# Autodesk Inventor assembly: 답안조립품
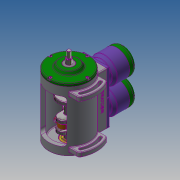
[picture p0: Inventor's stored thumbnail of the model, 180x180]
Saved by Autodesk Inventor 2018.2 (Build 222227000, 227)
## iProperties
Created: 2022-01
Part Number: 답안조립품
Document SubType Name: Assembly
Designer: woori
Mass: 7371.38 g
Surface Area: 5215.18 cm^2
Volume: 2062.2 cm^3
Density: 3.57452 g/cm^3
Author: woori
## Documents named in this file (16)
- C:\Users\woori\Desktop\620106V1013\답안조립품.iam
- C:\Users\woori\Desktop\620106V1013\본체.ipt
- C:\Users\woori\Desktop\620106V1013\앞커버.ipt
- C:\Users\woori\Desktop\620106V1013\크랭크축.ipt
- C:\Users\woori\Desktop\620106V1013\실린더.ipt
- C:\Users\woori\Desktop\620106V1013\피스톤.ipt
- C:\Users\woori\Desktop\620106V1013\피스톤핀.ipt
- C:\Users\woori\Desktop\620106V1013\실린더헤드.ipt
- C:\Users\woori\Desktop\620106V1013\커넥팅로드.ipt
- C:\Users\woori\Desktop\620106V1013\커넥팅로드 엔드.ipt
- C:\Users\woori\Desktop\620106V1013\베어링 6303.ipt
- C:\Users\woori\Desktop\620106V1013\오일 실 17 x 32 x 8.ipt
- C:\Users\woori\Desktop\620106V1013\육각 머리 볼트 M4 x 16.ipt
- C:\Users\woori\Desktop\620106V1013\너트 M4.ipt
- C:\Users\woori\Desktop\620106V1013\볼트 M4 x 12.ipt
- C:\Users\woori\Desktop\620106V1013\볼트 M5 x 20.ipt
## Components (4 placed, 2 different names)
1. 피스톤:1
2. 피스톤:2
3. 피스톤핀:1
4. 피스톤핀:2
